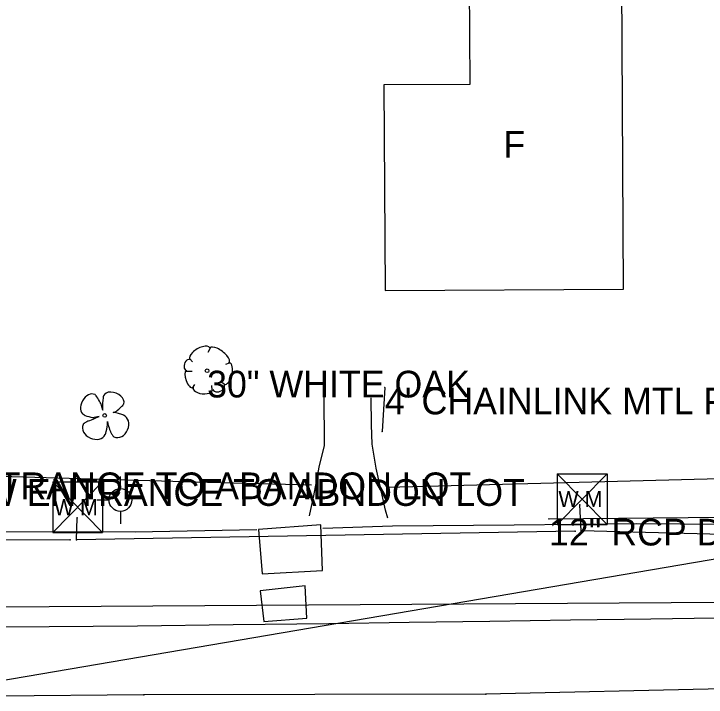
# Model space of a CAD drawing. Extents: x 1304270 to 1306561, y 1876019 to 1876752.
# Drawn here: x 1306055.3 to 1306184.9, y 1876398.6 to 1876526.4 of the extents above; entities that cross this region are included whole.
import ezdxf

# ---------------------------------------------------------------- set-up
doc = ezdxf.new("R2010")
doc.units = 0
for name, color, linetype in [('Default', 7, 'Continuous'), ('S_BUILDING', 7, 'Continuous'), ('S_BUILDING_ANNOT', 7, 'Continuous'), ('S_DRIVEWAY', 7, 'Continuous'), ('S_EDGE_CONCRETE', 7, 'Continuous'), ('S_EDGE_PAVEMENT', 7, 'Continuous'), ('S_FENCE', 7, 'Continuous'), ('S_FENCE_ANNOT', 7, 'Continuous'), ('S_FIBER_OPTIC_CABLE', 7, 'Continuous'), ('S_MSC_PT_SYM', 7, 'Continuous'), ('S_PAVEMENT_CROWN', 7, 'Continuous'), ('S_SANITARY_SEWER', 7, 'Continuous'), ('S_STORM_SEWER', 7, 'Continuous'), ('S_STORM_SEWER_ANNOT', 7, 'Continuous'), ('S_SURVEY_TEXT_ANNOT', 7, 'Continuous'), ('S_TRAILS', 7, 'Continuous'), ('S_TREE', 7, 'Continuous'), ('S_TREE_ANNOT', 7, 'Continuous'), ('S_UTILITY_POLE', 7, 'Continuous'), ('S_UTL_PT_SYM', 7, 'Continuous'), ('S_WATER_UTILITIES', 7, 'Continuous')]:
    doc.layers.add(name, color=color, linetype=linetype)

msp = doc.modelspace()

# ---------------------------------------------------------------- linework, layer by layer
at = {"layer": 'Default'}
msp.add_line((1305993.25, 1876391.55), (1306312.09, 1876445.88), dxfattribs=at)
at = {"layer": 'S_BUILDING'}
msp.add_lwpolyline([(1306169.41, 1876474.94), (1306169.05, 1876532.19), (1306140.49, 1876532.01), (1306140.61, 1876513.24), (1306124.53, 1876513.14), (1306124.77, 1876474.66)], close=True, dxfattribs=at)
at = {"layer": 'S_DRIVEWAY'}
for points in [[(1306113.3, 1876455.21), (1306113.35, 1876445.68), (1306112.38, 1876441.64), (1306111.36, 1876436.24), (1306110.82, 1876433.72), (1306110.56, 1876432.51)], [(1306125.28, 1876432.08), (1306124.86, 1876433.56), (1306123.13, 1876441.46), (1306122.35, 1876445.93), (1306122.22, 1876449.54), (1306122.2, 1876454.59)]]:
    msp.add_lwpolyline(points, dxfattribs=at)
at = {"layer": 'S_EDGE_CONCRETE'}
for points in [[(1306101.09, 1876429.97), (1306101.78, 1876421.68), (1306113.07, 1876422.32), (1306112.73, 1876430.87)], [(1306112.73, 1876430.87), (1306101.09, 1876429.97)]]:
    msp.add_lwpolyline(points, dxfattribs=at)
msp.add_lwpolyline([(1306101.4, 1876418.49), (1306102.07, 1876412.78), (1306110.14, 1876413.4), (1306109.84, 1876419.46)], close=True, dxfattribs=at)
at = {"layer": 'S_EDGE_PAVEMENT'}
for points in [[(1306113.12, 1876430.25), (1306126.16, 1876430.64), (1306148.96, 1876430.86), (1306171.76, 1876431.08), (1306196.43, 1876430.92), (1306201.22, 1876431.25), (1306201.59, 1876430.5), (1306204.64, 1876430.62), (1306209.26, 1876430.77), (1306212.62, 1876431.11), (1306218.85, 1876431.26), (1306235.37, 1876431.61), (1306256.72, 1876432.09), (1306262.37, 1876432.42), (1306275.55, 1876432.51), (1306288.74, 1876432.59), (1306294.65, 1876432.63), (1306294.99, 1876432.68), (1306300.36, 1876432.78), (1306312.86, 1876432.81), (1306325.37, 1876432.84), (1306326.28, 1876432.72), (1306334.35, 1876433.02), (1306341.35, 1876433.31)], [(1305950.89, 1876427.47), (1305964.22, 1876427.79), (1305977.54, 1876428.11), (1305992.2, 1876428.56), (1306006.85, 1876429.02), (1306028.93, 1876429.57), (1306053.46, 1876429.57), (1306077.99, 1876429.56), (1306100.79, 1876429.97)]]:
    msp.add_lwpolyline(points, dxfattribs=at)
at = {"layer": 'S_FENCE'}
msp.add_line((1306124.74, 1876456.51), (1306124.2, 1876448.28), dxfattribs=at)
msp.add_lwpolyline([(1306124.74, 1876456.51), (1306124.2, 1876448.28)], dxfattribs=at)
msp.add_lwpolyline([(1306124.74, 1876456.51), (1306124.2, 1876448.28)], dxfattribs=at)
at = {"layer": 'S_FIBER_OPTIC_CABLE'}
for p, q in [((1306202.94, 1876400.5), (1306143.64, 1876399.14)), ((1306079.65, 1876399.02), (1306046.32, 1876398.72)), ((1306143.64, 1876399.14), (1306079.65, 1876399.02))]:
    msp.add_line(p, q, dxfattribs=at)
at = {"layer": 'S_MSC_PT_SYM'}
for points in [[(1306124.74, 1876456.51), (1306124.74, 1876456.56), (1306124.74, 1876456.51), (1306124.69, 1876456.51), (1306124.74, 1876456.51), (1306124.74, 1876456.46), (1306124.74, 1876456.51), (1306124.79, 1876456.51)], [(1306124.2, 1876448.28), (1306124.2, 1876448.33), (1306124.2, 1876448.28), (1306124.15, 1876448.28), (1306124.2, 1876448.28), (1306124.2, 1876448.23), (1306124.2, 1876448.28), (1306124.25, 1876448.28)]]:
    msp.add_lwpolyline(points, dxfattribs=at)
at = {"layer": 'S_PAVEMENT_CROWN'}
msp.add_lwpolyline([(1306053.64, 1876411.74), (1306078.45, 1876411.98), (1306096.34, 1876412.19), (1306114.22, 1876412.39), (1306129.3, 1876412.61), (1306144.38, 1876412.83), (1306159.45, 1876413.06), (1306174.53, 1876413.28), (1306194.7, 1876413.58), (1306214.87, 1876413.88), (1306234.9, 1876413.74), (1306250.98, 1876414.03), (1306267.06, 1876414.33), (1306289.97, 1876414.14), (1306302.49, 1876414.59), (1306315, 1876415.05), (1306334.8, 1876415.21), (1306354.59, 1876415.38)], dxfattribs=at)
at = {"layer": 'S_SANITARY_SEWER'}
msp.add_line((1306231.1, 1876416.56), (1305933.99, 1876414.7), dxfattribs=at)
at = {"layer": 'S_STORM_SEWER'}
msp.add_line((1306155.44, 1876431.98), (1306202.78, 1876432.42), dxfattribs=at)
at = {"layer": 'S_TRAILS'}
for points in [[(1306033.26, 1876440.47), (1306052.69, 1876439.93), (1306072.13, 1876439.39), (1306091.56, 1876438.85), (1306111, 1876438.31)], [(1306125.18, 1876437.88), (1306204.2, 1876439.95)]]:
    msp.add_lwpolyline(points, dxfattribs=at)
at = {"layer": 'S_TREE'}
for p, q in [((1306092.03, 1876463.91), (1306091.64, 1876463.06)), ((1306088.23, 1876461.9), (1306088.73, 1876461.32)), ((1306095.59, 1876461.12), (1306094.93, 1876460.85)), ((1306087.57, 1876459.57), (1306088.7, 1876459.57)), ((1306088.73, 1876456.4), (1306089.2, 1876457.09)), ((1306092.42, 1876456.12), (1306092.34, 1876456.9)), ((1306094.82, 1876457.02), (1306094.35, 1876457.44)), ((1306071.94, 1876452.3), (1306071.7, 1876453.19)), ((1306073.89, 1876451.84), (1306074.27, 1876452)), ((1306071.29, 1876451.14), (1306070.32, 1876450.92)), ((1306072.83, 1876450.2), (1306072.9, 1876449.77))]:
    msp.add_line(p, q, dxfattribs=at)
for centre in [(1306091.47, 1876459.67), (1306072.31, 1876451.32)]:
    msp.add_circle(centre, 0.341, dxfattribs=at)
for centre, major_axis, ratio, start_param, end_param in [((1306090.13, 1876462.87), (1.86, 1.08), 0.471018, 0, 3.141593), ((1306093.79, 1876462.55), (-1.81, 1.36), 0.405113, 3.141593, 6.283186), ((1306087.9, 1876460.75), (0.31, 1.03), 0.646762, 0, 3.141593), ((1306095.14, 1876459.14), (0.46, 2.04), 0.482994, 3.141593, 6.283185), ((1306088.2, 1876458.1), (-0.61, 1.6), 0.420543, 6.283185, 9.424777), ((1306093.62, 1876456.62), (1.09, 0.46), 0.711534, 3.141592, 6.283185), ((1306069.42, 1876453.34), (-1.03, -1.88), 0.662338, 3.141593, 6.283185), ((1306073.97, 1876454.21), (1.89, -0.74), 0.673998, 0, 3.141593), ((1306090.67, 1876456.32), (-1.83, 0.19), 0.529943, 0, 3.141593), ((1306071.08, 1876454.21), (0.62, -1.01), 0.083512, 0, 3.141593), ((1306072.01, 1876453.62), (-0.07, -1.33), 0.068203, 3.141593, 6.283185), ((1306075.07, 1876452.73), (-0.798, -0.73), 0.092159, 0, 3.141593), ((1306074.85, 1876451.61), (0.96, -0.23), 0.056001, 0, 3.141593), ((1306069.35, 1876451.19), (0.964, -0.267), 0.113563, 3.141593, 6.283185), ((1306070.25, 1876450.69), (1.04, 0.44), 0.002756, 3.141593, 6.283185), ((1306074.93, 1876449.33), (0.88, 2.05), 0.81717, 3.141593, 6.283185), ((1306070.33, 1876448.66), (2.07, -0.93), 0.760068, 3.141593, 6.283185), ((1306068.74, 1876449.92), (0.477, 0.328), 0.136309, 0, 3.141593), ((1306072.59, 1876449.04), (0.19, 1.31), 0.114148, 3.141593, 5.822668), ((1306073.16, 1876448.99), (0.254, -0.771), 0.051603, 3.141593, 6.283185), ((1306073.73, 1876447.76), (-0.321, 0.467), 0.094289, 0, 3.141593)]:
    msp.add_ellipse(centre, major_axis=major_axis, ratio=ratio, start_param=start_param, end_param=end_param, dxfattribs=at)
at = {"layer": 'S_UTILITY_POLE'}
for p, q in [((1306075.25, 1876437.61), (1306075.25, 1876439.86)), ((1306073.15, 1876435.48), (1306070.83, 1876435.48)), ((1306075.32, 1876431.06), (1306075.32, 1876433.39))]:
    msp.add_line(p, q, dxfattribs=at)
msp.add_circle((1306075.25, 1876435.5), 2.13, dxfattribs=at)
at = {"layer": 'S_UTL_PT_SYM'}
for points in [[(1306161.2, 1876434.58), (1306161.2, 1876434.63), (1306161.2, 1876434.58), (1306161.15, 1876434.58), (1306161.2, 1876434.58), (1306161.2, 1876434.53), (1306161.2, 1876434.58), (1306161.25, 1876434.58)], [(1306067.16, 1876432.16), (1306067.16, 1876432.21), (1306067.16, 1876432.16), (1306067.11, 1876432.16), (1306067.16, 1876432.16), (1306067.16, 1876432.11), (1306067.16, 1876432.16), (1306067.21, 1876432.16)], [(1306155.44, 1876431.98), (1306155.44, 1876432.03), (1306155.44, 1876431.98), (1306155.39, 1876431.98), (1306155.44, 1876431.98), (1306155.44, 1876431.93), (1306155.44, 1876431.98), (1306155.49, 1876431.98)], [(1306160.34, 1876429.67), (1306160.34, 1876429.72), (1306160.34, 1876429.67), (1306160.29, 1876429.67), (1306160.34, 1876429.67), (1306160.34, 1876429.62), (1306160.34, 1876429.67), (1306160.39, 1876429.67)], [(1306161.44, 1876429.71), (1306161.44, 1876429.76), (1306161.44, 1876429.71), (1306161.39, 1876429.71), (1306161.44, 1876429.71), (1306161.44, 1876429.66), (1306161.44, 1876429.71), (1306161.49, 1876429.71)], [(1306065.82, 1876428.03), (1306065.82, 1876428.08), (1306065.82, 1876428.03), (1306065.77, 1876428.03), (1306065.82, 1876428.03), (1306065.82, 1876427.98), (1306065.82, 1876428.03), (1306065.87, 1876428.03)], [(1306067.02, 1876428.05), (1306067.02, 1876428.1), (1306067.02, 1876428.05), (1306066.97, 1876428.05), (1306067.02, 1876428.05), (1306067.02, 1876428), (1306067.02, 1876428.05), (1306067.07, 1876428.05)], [(1306079.65, 1876399.02), (1306079.65, 1876399.07), (1306079.65, 1876399.02), (1306079.6, 1876399.02), (1306079.65, 1876399.02), (1306079.65, 1876398.97), (1306079.65, 1876399.02), (1306079.7, 1876399.02)], [(1306143.64, 1876399.14), (1306143.64, 1876399.19), (1306143.64, 1876399.14), (1306143.59, 1876399.14), (1306143.64, 1876399.14), (1306143.64, 1876399.09), (1306143.64, 1876399.14), (1306143.69, 1876399.14)]]:
    msp.add_lwpolyline(points, dxfattribs=at)
at = {"layer": 'S_WATER_UTILITIES'}
for p, q in [((1306157, 1876440.39), (1306166.34, 1876440.39)), ((1306157, 1876440.39), (1306157, 1876430.9)), ((1306157, 1876440.39), (1306166.34, 1876430.9)), ((1306166.34, 1876440.39), (1306157, 1876430.9)), ((1306166.34, 1876440.39), (1306166.34, 1876430.9)), ((1306062.59, 1876438.88), (1306071.93, 1876438.88)), ((1306062.59, 1876438.88), (1306062.59, 1876429.39)), ((1306062.59, 1876438.88), (1306071.93, 1876429.39)), ((1306071.93, 1876438.88), (1306062.59, 1876429.39)), ((1306071.93, 1876438.88), (1306071.93, 1876429.39)), ((1306161.44, 1876429.71), (1306161.2, 1876434.58)), ((1306067.02, 1876428.05), (1306067.16, 1876432.16)), ((1306157, 1876430.9), (1306166.34, 1876430.9)), ((1306160.34, 1876429.67), (1306067.02, 1876428.05)), ((1306199.48, 1876428.72), (1306161.44, 1876429.71)), ((1306062.59, 1876429.39), (1306071.93, 1876429.39)), ((1306065.82, 1876428.03), (1306005.31, 1876427.67))]:
    msp.add_line(p, q, dxfattribs=at)

# ---------------------------------------------------------------- texts
at = {"layer": 'S_BUILDING_ANNOT'}
msp.add_text('F', height=5, dxfattribs=at).set_placement((1306146.91, 1876499.53))
at = {"layer": 'S_FENCE_ANNOT'}
msp.add_text("4' CHAINLINK MTL POST POOR", height=5, dxfattribs=at).set_placement((1306124.74, 1876451.51))
at = {"layer": 'S_STORM_SEWER_ANNOT'}
msp.add_text('12" RCP DIRECTION ONLY', height=5, dxfattribs=at).set_placement((1306155.44, 1876426.98))
at = {"layer": 'S_SURVEY_TEXT_ANNOT'}
for s, p in [('GRVL DW ENTRANCE TO ABANDON LOT', (1306010.13, 1876435.64)), ('GRVL DW ENTRANCE TO ABNDON LOT', (1306024.64, 1876434.39))]:
    msp.add_text(s, height=5, dxfattribs=at).set_placement(p)
at = {"layer": 'S_TREE_ANNOT'}
msp.add_text('30" WHITE OAK', height=5, dxfattribs=at).set_placement((1306091.47, 1876454.67))
at = {"layer": 'S_WATER_UTILITIES'}
for p in [(1306157.21, 1876434.16), (1306062.79, 1876432.65)]:
    msp.add_text('W M', height=3, rotation=360, dxfattribs=at).set_placement(p)

doc.saveas('drawing.dxf')
